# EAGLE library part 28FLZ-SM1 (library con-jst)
CONNECTOR
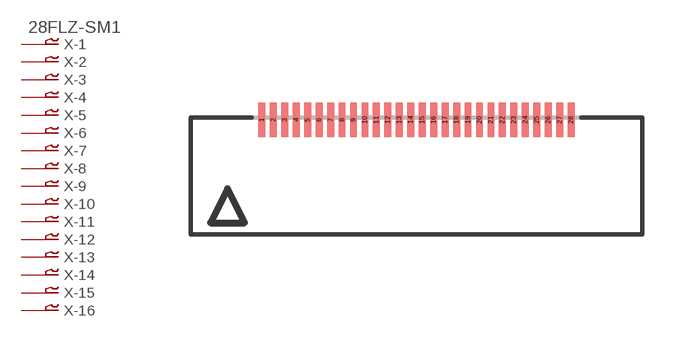
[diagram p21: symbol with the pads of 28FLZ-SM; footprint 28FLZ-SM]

Designator prefix X; gates -1=P-VN -2=P-N -3=P-N -4=P-N -5=P-N -6=P-N -7=P-N -8=P-N -9=P-N -10=P-N -11=P-N -12=P-N -13=P-N -14=P-N -15=P-N -16=P-N -17=P-N -18=P-N -19=P-N -20=P-N -21=P-N -22=P-N -23=P-N -24=P-N -25=P-N -26=P-N -27=P-N -28=P-N

## 28FLZ-SM1 (OC_FARNELL: unknown; OC_NEWARK: unknown)  [28FLZ-SM]
1  -1:1  pas
2  -2:1  pas
3  -3:1  pas
4  -4:1  pas
5  -5:1  pas
6  -6:1  pas
7  -7:1  pas
8  -8:1  pas
9  -9:1  pas
10  -10:1  pas
11  -11:1  pas
12  -12:1  pas
13  -13:1  pas
14  -14:1  pas
15  -15:1  pas
16  -16:1  pas
17  -17:1  pas
18  -18:1  pas
19  -19:1  pas
20  -20:1  pas
21  -21:1  pas
22  -22:1  pas
23  -23:1  pas
24  -24:1  pas
25  -25:1  pas
26  -26:1  pas
27  -27:1  pas
28  -28:1  pas

## Footprint 28FLZ-SM (pad centres in mm)
CONNECTOR
smd 0.3 x 1.5: 1 -6.75,2.5; 2 -6.25,2.5; 3 -5.75,2.5; 4 -5.25,2.5; 5 -4.75,2.5; 6 -4.25,2.5; 7 -3.75,2.5; 8 -3.25,2.5; 9 -2.75,2.5; 10 -2.25,2.5; 11 -1.75,2.5; 12 -1.25,2.5; 13 -0.75,2.5; 14 -0.25,2.5; 15 0.25,2.5; 16 0.75,2.5; 17 1.25,2.5; 18 1.75,2.5; 19 2.25,2.5; 20 2.75,2.5; 21 3.25,2.5; 22 3.75,2.5; 23 4.25,2.5; 24 4.75,2.5; 25 5.25,2.5; 26 5.75,2.5; 27 6.25,2.5; 28 6.75,2.5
